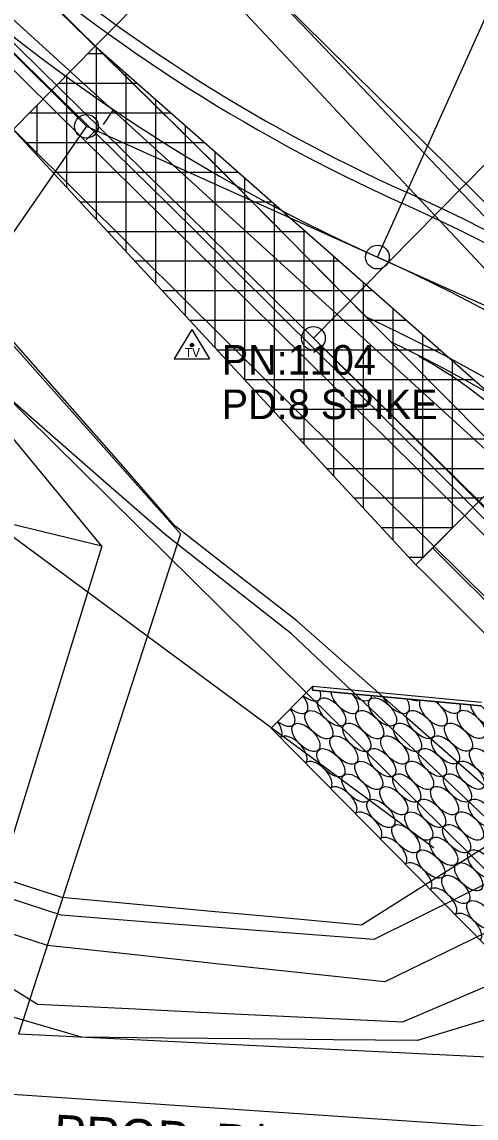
# Model space of a CAD drawing. Extents: x 1660112 to 1662239, y 668919 to 671377.
# Drawn here: x 1661159 to 1661235.6, y 670188.6 to 670373.6 of the extents above; entities that cross this region are included whole.
import ezdxf

# ---------------------------------------------------------------- set-up
doc = ezdxf.new("R2010")
doc.units = 0
for name, color, linetype in [('R_Annotation', 7, 'Continuous'), ('R_Axis', 7, 'Continuous'), ('R_Concrete', 7, 'Continuous'), ('R_Horz Alg', 7, 'Continuous'), ('R_Horz Alg Annot', 7, 'Continuous'), ('R_Proposed Const Limits_Cut', 7, 'Continuous'), ('R_Proposed Const Limits_Hand', 7, 'Continuous'), ('R_Proposed Road_Lane', 7, 'Continuous'), ('R_Proposed Road_Shoulder', 7, 'Continuous'), ('R_ROW', 7, 'Continuous'), ('R_ROW Annot', 7, 'Continuous'), ('R_Water Annot', 7, 'Continuous'), ('S_BASELINE', 7, 'Continuous'), ('S_DITCHLINE', 7, 'Continuous'), ('S_EDGE_PAVEMENT', 7, 'Continuous'), ('S_EXIST_ROW', 7, 'Continuous'), ('S_EXISTING_ALIGNMENT', 7, 'Continuous'), ('S_PAVEMENT_CROWN', 7, 'Continuous'), ('S_SECONDARY_CTL', 7, 'Continuous'), ('S_SECONDARY_CTL_ANNOT', 7, 'Continuous'), ('S_STREAM', 7, 'Continuous'), ('S_UTL_PT_SYM', 7, 'Continuous'), ('S_WATER_UTILITIES', 7, 'Continuous')]:
    doc.layers.add(name, color=color, linetype=linetype)

msp = doc.modelspace()

# ---------------------------------------------------------------- linework, layer by layer
at = {"layer": 'R_Axis'}
for p, q in [((1661170.19, 670368.25), (1661172.82, 670368.25)), ((1661171.63, 670340.24), (1661171.63, 670369.29)), ((1661166.63, 670345.65), (1661166.63, 670364.64)), ((1661176.63, 670334.83), (1661176.63, 670364.89)), ((1661165.26, 670363.25), (1661178.49, 670363.25)), ((1661161.63, 670351.06), (1661161.63, 670359.57)), ((1661181.63, 670329.42), (1661181.63, 670360.48)), ((1661160.34, 670358.25), (1661184.17, 670358.25)), ((1661186.63, 670324.01), (1661186.63, 670356.08)), ((1661159.61, 670353.25), (1661189.85, 670353.25)), ((1661191.63, 670318.6), (1661191.63, 670351.68)), ((1661164.23, 670348.25), (1661195.53, 670348.25)), ((1661196.63, 670313.19), (1661196.63, 670347.28)), ((1661168.85, 670343.25), (1661201.21, 670343.25)), ((1661201.63, 670307.78), (1661201.63, 670342.87)), ((1661206.63, 670302.37), (1661206.63, 670338.47)), ((1661173.47, 670338.25), (1661206.89, 670338.25)), ((1661178.09, 670333.25), (1661212.56, 670333.25)), ((1661211.63, 670296.96), (1661211.63, 670334.07)), ((1661216.63, 670291.55), (1661216.63, 670329.66)), ((1661182.71, 670328.25), (1661218.24, 670328.25)), ((1661221.63, 670286.14), (1661221.63, 670325.26)), ((1661187.34, 670323.25), (1661223.92, 670323.25)), ((1661226.63, 670283.15), (1661226.63, 670320.86)), ((1661191.96, 670318.25), (1661229.6, 670318.25)), ((1661231.63, 670288.18), (1661231.63, 670316.46)), ((1661196.58, 670313.25), (1661235.28, 670313.25)), ((1661201.2, 670308.25), (1661240.96, 670308.25)), ((1661205.82, 670303.25), (1661246.63, 670303.25)), ((1661210.44, 670298.25), (1661241.66, 670298.25)), ((1661215.06, 670293.25), (1661236.68, 670293.25)), ((1661219.68, 670288.25), (1661231.71, 670288.25)), ((1661224.3, 670283.25), (1661226.73, 670283.25))]:
    msp.add_line(p, q, dxfattribs=at)
msp.add_lwpolyline([(1661157.58, 670355.45), (1661171.41, 670369.49), (1661246.63, 670303.25), (1661225.47, 670281.99)], close=True, dxfattribs=at)
at = {"layer": 'R_Concrete'}
for p, q in [((1661208.1, 670261.48), (1661208.04, 670260.82)), ((1661208.1, 670261.48), (1661208.04, 670260.82)), ((1661208.04, 670260.82), (1661236.51, 670258.15)), ((1661208.04, 670260.82), (1661236.51, 670258.15)), ((1661208.1, 670261.48), (1661236.56, 670258.81)), ((1661208.1, 670261.48), (1661236.56, 670258.81))]:
    msp.add_line(p, q, dxfattribs=at)
at = {"layer": 'R_Horz Alg'}
msp.add_line((1661029.53, 670496.2), (1661208.2, 670320.2), dxfattribs=at)
for centre, radius, start, end in [((1661339.53, 670601.86), 293.82, 225.0245, 245.7806), ((1661098.46, 670065.94), 293.82, 23.4717, 65.7806), ((1655846.99, 664877.91), 7639.44, 42.561815, 45.430038)]:
    msp.add_arc(centre, radius, start, end, dxfattribs=at)
at = {"layer": 'R_Horz Alg Annot'}
for p, q in [((1661131.85, 670394.01), (1661169.92, 670355.98)), ((1661218.99, 670333.9), (1661239.73, 670380.01)), ((1661169.92, 670355.98), (1661218.99, 670333.9)), ((1661218.99, 670333.9), (1661322.68, 670287.26)), ((1661208.2, 670320.2), (1661344.44, 670185.98))]:
    msp.add_line(p, q, dxfattribs=at)
for points in [[(1661292.41, 670405.69), (1661208.2, 670320.2)], [(1661172.8, 670356.29), (1661174.48, 670358.77)], [(1661169.92, 670355.98), (1661101.78, 670257.2)], [(1661169.9, 670353.71), (1661172.01, 670355.85)]]:
    msp.add_lwpolyline(points, dxfattribs=at)
for centre in [(1661169.92, 670355.98), (1661218.99, 670333.9), (1661208.2, 670320.2)]:
    msp.add_circle(centre, 2, dxfattribs=at)
at = {"layer": 'R_Proposed Const Limits_Cut'}
for p in [(1661185.76, 670287.22), (1661254.1, 670198.04)]:
    msp.add_line(p, (1661158.47, 670202.77), dxfattribs=at)
for points in [[(1661171.41, 670369.49), (1661191.23, 670389.52), (1661303.34, 670360.22), (1661343.39, 670328.65)], [(1661185.76, 670287.22), (1661139.85, 670338.9), (1661157.58, 670355.45)]]:
    msp.add_lwpolyline(points, dxfattribs=at)
at = {"layer": 'R_Proposed Const Limits_Hand'}
msp.add_lwpolyline([(1661225.96, 670317.2), (1661226.14, 670317.1), (1661228.82, 670315.55), (1661230.24, 670314.68), (1661231.63, 670313.81), (1661234.35, 670311.91), (1661236.98, 670309.86)], dxfattribs=at)
at = {"layer": 'R_Proposed Road_Lane'}
msp.add_line((1661228.29, 670284.82), (1661243.81, 670300.41), dxfattribs=at)
msp.add_lwpolyline([(1661221.24, 670319.61), (1661196.18, 670344.94), (1661186.67, 670354.44), (1661139.21, 670401.37)], dxfattribs=at)
for centre, radius, start, end in [((1661339.53, 670601.86), 283.82, 228.2052, 245.7806), ((1661098.46, 670065.94), 303.82, 23.4717, 65.7806), ((1661098.46, 670065.94), 283.82, 24.6629, 65.2815), ((1655846.99, 664877.91), 7628.44, 44.123518, 45.136018)]:
    msp.add_arc(centre, radius, start, end, dxfattribs=at)
at = {"layer": 'R_Proposed Road_Shoulder'}
msp.add_line((1661228.29, 670284.82), (1661225.47, 670281.99), dxfattribs=at)
for centre, radius, start, end in [((1661339.53, 670601.86), 281.82, 228.4276, 245.7806), ((1661098.46, 670065.94), 305.82, 23.4717, 65.7806), ((1661098.46, 670065.94), 281.82, 25.8293, 64.1706), ((1655846.99, 664877.91), 7624.44, 44.123518, 45.136018)]:
    msp.add_arc(centre, radius, start, end, dxfattribs=at)
at = {"layer": 'R_ROW'}
for p in [(1661172.54, 670285.14), (1661242.56, 670186.79)]:
    msp.add_line(p, (1661144.3, 670193.47), dxfattribs=at)
msp.add_lwpolyline([(1661172.54, 670285.14), (1661130.97, 670335.56)], dxfattribs=at)
at = {"layer": 'R_ROW Annot'}
msp.add_line((1661172.54, 670285.14), (1661148.63, 670290.92), dxfattribs=at)
at = {"layer": 'R_Water Annot'}
msp.add_lwpolyline([(1661208.1, 670261.48), (1661201.05, 670254.4), (1661266.25, 670188.25), (1661273.39, 670195.25), (1661272.84, 670195.64), (1661283.61, 670210.8), (1661236.51, 670258.15), (1661208.04, 670260.82)], close=True, dxfattribs=at)
for centre, start_param, end_param in [((1661207.09, 670261.4), 1.795421, 3.951549), ((1661204.91, 670259.25), 1.805687, 4.487507), ((1661213.48, 670259.27), 0.548587, 4.644724), ((1661215.66, 670261.41), 1.641365, 3.551946), ((1661222.05, 670259.29), 0.929494, 4.263817), ((1661224.23, 670261.43), 2.249999, 2.943312), ((1661228.44, 670257.16), 0.147326, 5.045985), ((1661230.62, 670259.3), 1.296061, 3.897249), ((1661202.73, 670257.1), 1.815978, 4.477216), ((1661237.01, 670257.18), 0.607063, 3.367089), ((1661200.55, 670254.95), 3.118049, 4.466899), ((1661204.76, 670250.68), 3.120012, 6.306733), ((1661208.97, 670246.4), 3.121974, 6.30477), ((1661213.18, 670242.13), 3.123937, 6.302807), ((1661217.39, 670237.85), 3.1259, 6.300845), ((1661221.6, 670233.58), 3.127862, 6.298882), ((1661225.81, 670229.3), 3.129825, 6.29692), ((1661230.02, 670225.03), 3.131787, 6.294957), ((1661234.23, 670220.75), 3.13375, 6.292995)]:
    msp.add_ellipse(centre, major_axis=(-2.1, 2.14), ratio=0.51, start_param=start_param, end_param=end_param, dxfattribs=at)
for centre in [(1661211.3, 670257.12), (1661219.87, 670257.14), (1661209.12, 670254.97), (1661217.69, 670254.99), (1661226.26, 670255.01), (1661234.83, 670255.03), (1661206.94, 670252.83), (1661215.51, 670252.85), (1661224.08, 670252.86), (1661232.65, 670252.88), (1661213.33, 670250.7), (1661221.9, 670250.72), (1661230.47, 670250.74), (1661211.15, 670248.55), (1661219.72, 670248.57), (1661228.29, 670248.59), (1661236.86, 670248.61), (1661217.54, 670246.42), (1661226.11, 670246.44), (1661234.68, 670246.46), (1661215.36, 670244.28), (1661223.93, 670244.29), (1661232.5, 670244.31), (1661221.75, 670242.15), (1661230.32, 670242.17), (1661219.57, 670240), (1661228.14, 670240.02), (1661236.71, 670240.04), (1661225.96, 670237.87), (1661234.53, 670237.89), (1661223.78, 670235.73), (1661232.35, 670235.74), (1661230.17, 670233.6), (1661227.99, 670231.45), (1661236.56, 670231.47), (1661234.38, 670229.32), (1661232.2, 670227.17), (1661236.41, 670222.9)]:
    msp.add_ellipse(centre, major_axis=(-2.1, 2.14), ratio=0.51, dxfattribs=at)
at = {"layer": 'S_BASELINE'}
msp.add_line((1660813.76, 670687.35), (1661335.19, 670212.07), dxfattribs=at)
at = {"layer": 'S_DITCHLINE'}
for points in [[(1661242.65, 670239.7), (1661224.03, 670256.09), (1661205.42, 670272.49), (1661195.13, 670280.52), (1661184.84, 670288.55), (1661175.36, 670299.38), (1661165.88, 670310.21), (1661156.4, 670321.03), (1661146.92, 670331.86), (1661137.55, 670341.19), (1661128.17, 670350.53), (1661118.79, 670359.86), (1661109.42, 670369.2), (1661097.31, 670380.98), (1661085.2, 670392.76), (1661068.34, 670408.15), (1661052.11, 670423.79), (1661035.88, 670439.43), (1661020.34, 670449.45), (1661008.68, 670464.67), (1660997.02, 670479.89), (1660983.41, 670495.38), (1660969.79, 670510.86)], [(1661239.43, 670237.24), (1661221.97, 670253.79), (1661204.51, 670270.33), (1661193.84, 670278.71), (1661183.17, 670287.08), (1661172.33, 670296.55), (1661161.49, 670306.02), (1661150.65, 670315.49), (1661139.81, 670324.96), (1661131.17, 670334.51), (1661122.52, 670344.05), (1661113.88, 670353.6), (1661105.24, 670363.14), (1661089.73, 670379.71), (1661086.66, 670381), (1661070.62, 670396.48), (1661054.58, 670411.96), (1661038.54, 670427.44), (1661022.5, 670442.92), (1661007.06, 670459.45), (1660991.62, 670475.99), (1660978.8, 670491.92), (1660965.98, 670507.85)], [(1661299.45, 670280.74), (1661284.47, 670292.7), (1661279.2, 670294.55), (1661276.17, 670300.4), (1661276.07, 670306.25), (1661258.9, 670321.05), (1661241.72, 670335.84), (1661231.17, 670346.95), (1661220.61, 670358.06), (1661210.06, 670369.17), (1661199.5, 670380.28), (1661190.45, 670390.39), (1661181.41, 670400.5), (1661172.36, 670410.61), (1661163.31, 670420.71), (1661149.32, 670433.4), (1661135.33, 670446.1), (1661121.34, 670458.79), (1661107.35, 670471.48)], [(1661292.16, 670275.66), (1661274.83, 670292.21), (1661270.79, 670300.84), (1661264.75, 670307.54), (1661250.97, 670319.7), (1661237.18, 670331.85), (1661227.07, 670342.64), (1661216.95, 670353.42), (1661206.84, 670364.21), (1661196.72, 670375), (1661186.88, 670384.5), (1661177.03, 670394.01), (1661167.19, 670403.51), (1661157.34, 670413.01), (1661144.39, 670427.16), (1661131.45, 670441.31), (1661118.5, 670455.46), (1661105.55, 670469.61)]]:
    msp.add_lwpolyline(points, dxfattribs=at)
at = {"layer": 'S_EDGE_PAVEMENT'}
for points in [[(1661249.53, 670264.29), (1661232.81, 670280.83), (1661216.09, 670297.37), (1661206.48, 670306.91), (1661196.87, 670316.45), (1661187.26, 670325.99), (1661177.65, 670335.53), (1661168.35, 670344.75), (1661159.06, 670353.98), (1661149.76, 670363.2), (1661140.47, 670372.43), (1661130.68, 670382.11), (1661120.89, 670391.8), (1661111.1, 670401.49), (1661101.31, 670411.17), (1661084.98, 670427.32), (1661068.65, 670443.47), (1661052.78, 670459.1), (1661036.91, 670474.73), (1661025.66, 670485.67), (1661014.42, 670496.6), (1661003.17, 670507.54), (1660991.93, 670518.47), (1660974.69, 670535.16)], [(1661262.8, 670277.66), (1661246.17, 670294.45), (1661229.53, 670311.23), (1661220, 670320.86), (1661210.47, 670330.49), (1661200.95, 670340.13), (1661191.42, 670349.76), (1661181.92, 670359.12), (1661172.42, 670368.49), (1661162.93, 670377.85), (1661153.43, 670387.22), (1661143.78, 670396.82), (1661134.14, 670406.42), (1661124.5, 670416.02), (1661114.85, 670425.63), (1661098.32, 670441.78), (1661081.78, 670457.93), (1661066.15, 670473.94), (1661050.52, 670489.95), (1661039.51, 670500.52), (1661028.5, 670511.09), (1661017.49, 670521.66), (1661006.48, 670532.23)]]:
    msp.add_lwpolyline(points, dxfattribs=at)
at = {"layer": 'S_EXIST_ROW'}
for p, q in [((1661404.92, 670177.11), (1660401.45, 671169.67)), ((1661347.41, 670121.48), (1660345.19, 671112.79))]:
    msp.add_line(p, q, dxfattribs=at)
at = {"layer": 'S_EXISTING_ALIGNMENT'}
msp.add_line((1661376.17, 670149.3), (1660373.32, 671141.23), dxfattribs=at)
at = {"layer": 'S_PAVEMENT_CROWN'}
msp.add_lwpolyline([(1661256.17, 670270.41), (1661239.48, 670287.26), (1661222.79, 670304.1), (1661213.05, 670313.75), (1661203.32, 670323.4), (1661193.59, 670333.05), (1661183.85, 670342.7), (1661174.57, 670351.81), (1661165.29, 670360.92), (1661156.01, 670370.03), (1661146.73, 670379.14), (1661137.08, 670388.79), (1661127.43, 670398.43), (1661117.78, 670408.07), (1661108.13, 670417.71), (1661091.69, 670433.83), (1661075.25, 670449.95), (1661059.39, 670465.57), (1661043.53, 670481.18), (1661032.32, 670491.86), (1661021.11, 670502.53), (1661009.9, 670513.21), (1660998.68, 670523.89), (1660981.9, 670540.69)], dxfattribs=at)
at = {"layer": 'S_SECONDARY_CTL'}
for p, q in [((1661187.72, 670321.67), (1661184.71, 670316.72)), ((1661187.72, 670321.67), (1661190.67, 670316.72)), ((1661184.71, 670316.72), (1661190.67, 670316.72))]:
    msp.add_line(p, q, dxfattribs=at)
for radius in [0.311, 0.183, 0.103]:
    msp.add_circle((1661187.72, 670319.06), radius, dxfattribs=at)
at = {"layer": 'S_STREAM'}
for points in [[(1661384.22, 670282.64), (1661367.85, 670280.4), (1661351.48, 670278.17), (1661335.11, 670275.93), (1661320.77, 670276.1), (1661306.42, 670276.27), (1661294.47, 670269.73), (1661282.53, 670263.19), (1661272.56, 670254.42), (1661262.59, 670245.66), (1661251.64, 670237.74), (1661240.7, 670229.82), (1661218.36, 670218.7), (1661205.19, 670219.73), (1661192.01, 670220.76), (1661178.84, 670221.78), (1661165.66, 670222.81), (1661153.9, 670226.65)], [(1661386.08, 670275.8), (1661370.4, 670273.52), (1661354.73, 670271.25), (1661339.06, 670268.97), (1661325.94, 670268.28), (1661312.82, 670267.6), (1661300.92, 670262.59), (1661289.01, 670257.59), (1661278.51, 670249.41), (1661268, 670241.23), (1661256.41, 670232.4), (1661244.82, 670223.57), (1661232.52, 670217.57), (1661220.23, 670211.57), (1661206.02, 670213.11), (1661191.8, 670214.64), (1661177.59, 670216.17), (1661163.37, 670217.71), (1661152.07, 670221.36)], [(1661387.42, 670269.33), (1661371.06, 670266.44), (1661354.71, 670263.56), (1661338.35, 670260.67), (1661316.6, 670255.88), (1661296.46, 670250.86), (1661285.68, 670241.86), (1661274.9, 670232.86), (1661258.9, 670220.78), (1661250.84, 670216.6), (1661237.04, 670210.68), (1661223.24, 670204.75), (1661207.85, 670205.5), (1661192.45, 670206.25), (1661177.06, 670207), (1661161.67, 670207.75), (1661149.8, 670215.11)], [(1661237.64, 670234.64), (1661226.98, 670227.9), (1661216.31, 670221.16), (1661203.67, 670222.32), (1661191.03, 670223.48), (1661178.4, 670224.64), (1661165.76, 670225.81), (1661154.74, 670229.38), (1661141.63, 670233.02), (1661128.51, 670236.67), (1661114.77, 670235.78), (1661104.13, 670231.11)], [(1661254.7, 670214.48), (1661247.25, 670208.21), (1661225.75, 670201.67), (1661211.58, 670201.81), (1661197.41, 670201.96), (1661183.24, 670202.1), (1661169.07, 670202.24), (1661154.61, 670206.46), (1661140.15, 670210.67), (1661126.98, 670218.08), (1661113.36, 670211.62), (1661104.67, 670201.88), (1661095.98, 670192.14), (1661082.19, 670186.21), (1661068.4, 670180.28), (1661054.61, 670174.34), (1661040.82, 670168.41), (1661022.25, 670157.95), (1661011.73, 670139.15), (1661001.22, 670120.35)]]:
    msp.add_lwpolyline(points, dxfattribs=at)
at = {"layer": 'S_UTL_PT_SYM'}
msp.add_lwpolyline([(1661228.37, 670234.25), (1661228.37, 670234.3), (1661228.37, 670234.25), (1661228.32, 670234.25), (1661228.37, 670234.25), (1661228.37, 670234.2), (1661228.37, 670234.25), (1661228.42, 670234.25)], dxfattribs=at)
at = {"layer": 'S_WATER_UTILITIES'}
msp.add_line((1661228.37, 670234.25), (1661041.63, 670372.43), dxfattribs=at)

# ---------------------------------------------------------------- texts
at = {"layer": 'R_Annotation'}
msp.add_text('PROP. R/W', height=6, rotation=356.8913, dxfattribs=at).set_placement((1661164.29, 670183.2))
at = {"layer": 'S_SECONDARY_CTL'}
msp.add_text('TV', height=1.5, rotation=360, dxfattribs=at).set_placement((1661186.52, 670317.05))
at = {"layer": 'S_SECONDARY_CTL_ANNOT'}
for s, p in [('PN:1104', (1661192.72, 670314.06)), ('PD:8 SPIKE', (1661192.72, 670306.56))]:
    msp.add_text(s, height=5, dxfattribs=at).set_placement(p)

doc.saveas('drawing.dxf')
